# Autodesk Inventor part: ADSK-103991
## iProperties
Shininess: 0.0
Created: 2000-11
Part Number: ADSK-103991
Document SubType Name: Modeling
Stock Number: ADSK-103991
Density: 1 g/cm^3
Density: 0.0
Volumn: 0.0
Area: 0.0
PropertySet Name: Model Information
Control State: 0
Master: False
Checked Out: False
Author: gao
